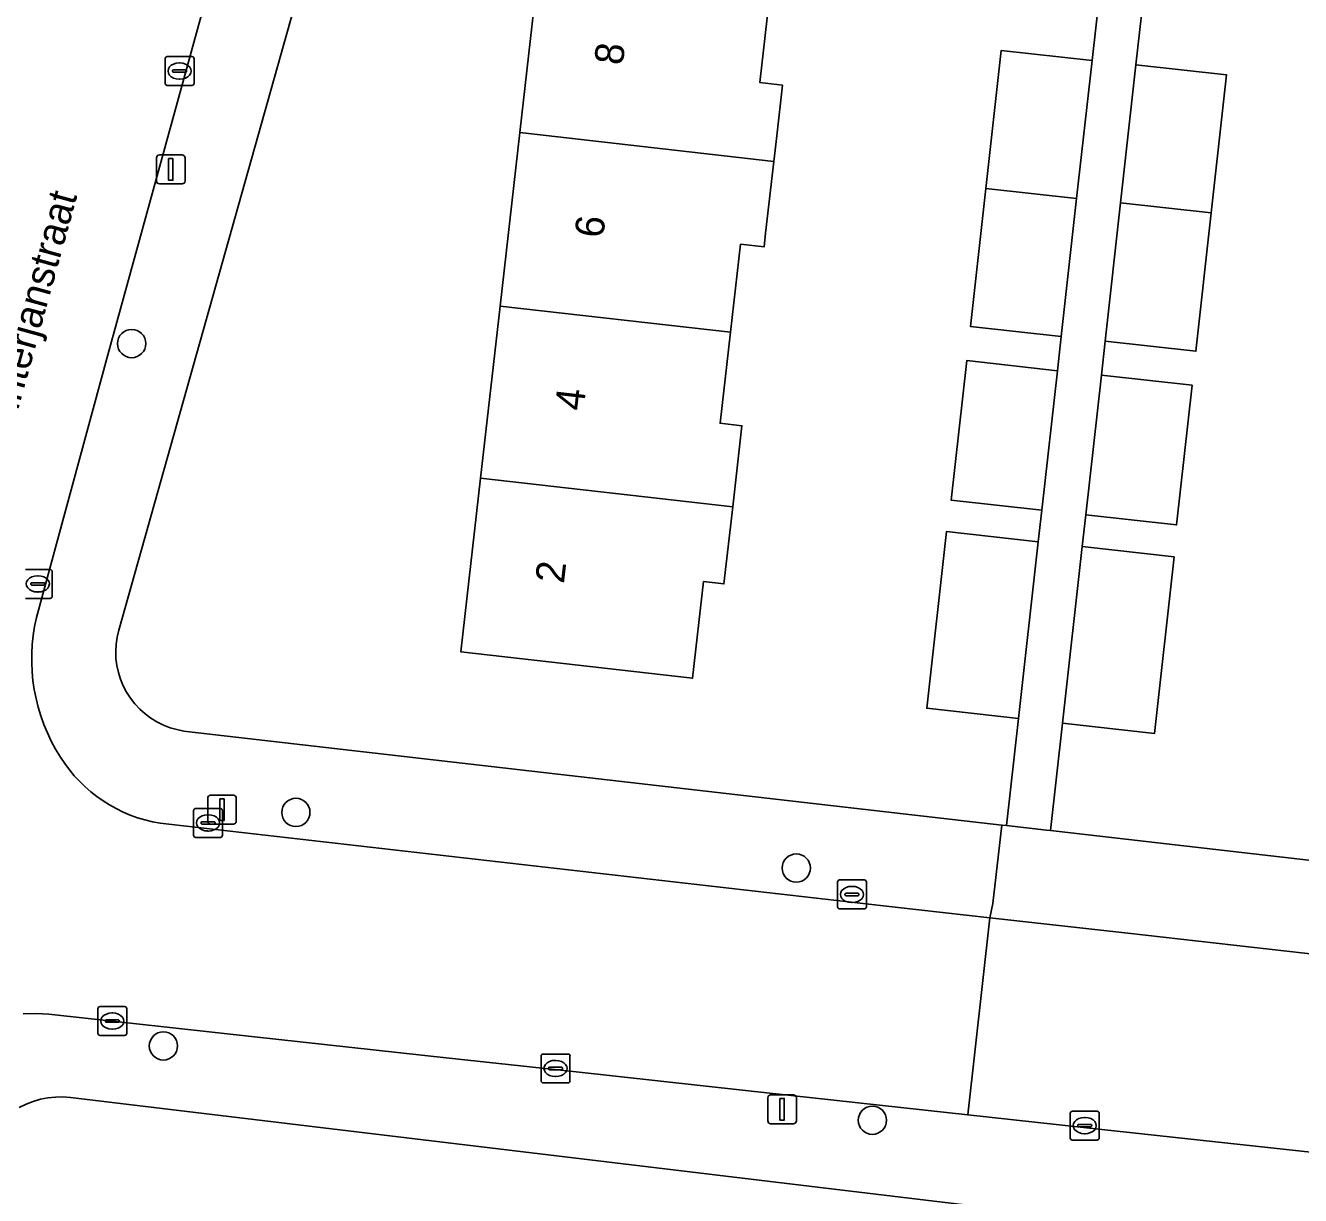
# Model space of a CAD drawing. Extents: x 162026 to 163502, y 387295 to 388169.
# Drawn here: x 162355.04 to 162399.19, y 387674.72 to 387715.23 of the extents above; entities that cross this region are included whole.
import ezdxf

# ---------------------------------------------------------------- set-up
doc = ezdxf.new("R2010")
doc.units = 0
for name, color, linetype in [('IMGEO_Boom', 7, 'Continuous'), ('IMGEO_Erf', 7, 'Continuous'), ('IMGEO_Kolk', 7, 'Continuous'), ('IMGEO_Lichtmast', 7, 'Continuous'), ('IMGEO_Openbare_ruimte_label', 7, 'Continuous'), ('IMGEO_Pand', 7, 'Continuous'), ('IMGEO_Pand_nummerreeks', 7, 'Continuous'), ('IMGEO_Rijbaan_lokaal_open', 7, 'Continuous'), ('IMGEO_Voetpad_open', 7, 'Continuous')]:
    doc.layers.add(name, color=color, linetype=linetype)

msp = doc.modelspace()

# ---------------------------------------------------------------- linework, layer by layer
at = {"layer": 'IMGEO_Boom'}
for centre in [(162358.717, 387704.216), (162364.402, 387687.982), (162381.73, 387686.057), (162359.815, 387679.899), (162384.363, 387677.325)]:
    msp.add_circle(centre, 0.489, dxfattribs=at)
at = {"layer": 'IMGEO_Erf'}
for points in [[(162369.363, 387733.695), (162358.268, 387694.296), (162358.211, 387694.055), (162358.176, 387693.81), (162358.163, 387693.562), (162358.172, 387693.315), (162358.204, 387693.069), (162358.257, 387692.827), (162358.331, 387692.591), (162358.427, 387692.362), (162358.542, 387692.143), (162358.676, 387691.935), (162358.829, 387691.74), (162358.998, 387691.559), (162359.183, 387691.394), (162359.382, 387691.247), (162359.593, 387691.117), (162359.815, 387691.007), (162360.046, 387690.917), (162360.284, 387690.849), (162360.527, 387690.801), (162360.613, 387690.79), (162388.85, 387687.545), (162389.013, 387687.526), (162389.427, 387691.233), (162386.247, 387691.587), (162386.929, 387697.705), (162390.109, 387697.35), (162390.232, 387698.447), (162387.091, 387698.797), (162387.63, 387703.627), (162390.771, 387703.277), (162390.902, 387704.455), (162387.762, 387704.805), (162388.295, 387709.586), (162388.828, 387714.366), (162391.969, 387714.016), (162392.234, 387716.39)], [(162405.775, 387731.887), (162398.802, 387732.687), (162398.12, 387726.557), (162394.939, 387726.911), (162394.814, 387725.788), (162397.955, 387725.438), (162397.423, 387720.658), (162396.89, 387715.867), (162393.749, 387716.217), (162393.488, 387713.868), (162396.629, 387713.519), (162396.097, 387708.738), (162395.564, 387703.95), (162392.423, 387704.299), (162392.292, 387703.124), (162395.433, 387702.775), (162394.895, 387697.939), (162391.754, 387698.288), (162391.631, 387697.184), (162394.812, 387696.83), (162394.131, 387690.714), (162390.951, 387691.068), (162390.537, 387687.351), (162410.507, 387685.056)], [(162380.837, 387716.521), (162380.466, 387713.255), (162381.25, 387713.166), (162381.05, 387711.409), (162380.949, 387710.524), (162380.667, 387708.041), (162380.613, 387707.564), (162379.797, 387707.656), (162379.45, 387704.609), (162379.092, 387701.456), (162379.849, 387701.37), (162379.529, 387698.56), (162379.226, 387695.893), (162378.519, 387695.973), (162378.139, 387692.627), (162370.115, 387693.539), (162370.798, 387699.552), (162371.475, 387705.514), (162372.158, 387711.522), (162372.829, 387717.43)], [(162386.507, 387674.529), (162356.601, 387678.112), (162356.339, 387678.132), (162356.076, 387678.128), (162355.815, 387678.1), (162355.557, 387678.05), (162355.305, 387677.976), (162355.06, 387677.88), (162354.825, 387677.763)]]:
    msp.add_lwpolyline(points, dxfattribs=at)
at = {"layer": 'IMGEO_Kolk'}
for p, q in [((162359.875, 387713.224), (162359.875, 387714.076)), ((162359.95, 387714.15), (162360.802, 387714.15)), ((162360.876, 387714.076), (162360.876, 387713.224)), ((162360.134, 387713.644), (162360.134, 387713.656)), ((162360.177, 387713.693), (162360.575, 387713.693)), ((162360.363, 387713.93), (162360.388, 387713.93)), ((162360.618, 387713.656), (162360.618, 387713.644)), ((162360.572, 387713.607), (162360.174, 387713.607)), ((162360.386, 387713.37), (162360.361, 387713.37)), ((162360.802, 387713.15), (162359.95, 387713.15)), ((162355.041, 387696.394), (162355.893, 387696.394)), ((162355.454, 387696.174), (162355.479, 387696.174)), ((162355.967, 387696.32), (162355.967, 387695.468)), ((162355.225, 387695.888), (162355.225, 387695.9)), ((162355.663, 387695.851), (162355.265, 387695.851)), ((162355.268, 387695.937), (162355.666, 387695.937)), ((162355.477, 387695.614), (162355.452, 387695.614)), ((162355.709, 387695.9), (162355.709, 387695.888)), ((162355.893, 387695.394), (162355.041, 387695.394)), ((162360.861, 387687.193), (162360.861, 387688.045)), ((162360.936, 387688.119), (162361.788, 387688.119)), ((162361.862, 387688.045), (162361.862, 387687.193)), ((162361.12, 387687.613), (162361.12, 387687.625)), ((162361.163, 387687.662), (162361.561, 387687.662)), ((162361.349, 387687.899), (162361.374, 387687.899)), ((162361.604, 387687.625), (162361.604, 387687.613)), ((162361.558, 387687.576), (162361.16, 387687.576)), ((162361.372, 387687.339), (162361.347, 387687.339)), ((162361.788, 387687.119), (162360.936, 387687.119)), ((162383.156, 387684.717), (162383.156, 387685.569)), ((162383.231, 387685.643), (162384.083, 387685.643)), ((162383.644, 387685.423), (162383.669, 387685.423)), ((162384.157, 387685.569), (162384.157, 387684.717)), ((162383.415, 387685.137), (162383.415, 387685.149)), ((162383.853, 387685.1), (162383.455, 387685.1)), ((162383.458, 387685.186), (162383.856, 387685.186)), ((162383.899, 387685.149), (162383.899, 387685.137)), ((162384.083, 387684.643), (162383.231, 387684.643)), ((162383.667, 387684.863), (162383.642, 387684.863)), ((162357.547, 387680.334), (162357.547, 387681.186)), ((162357.622, 387681.26), (162358.474, 387681.26)), ((162358.035, 387681.04), (162358.06, 387681.04)), ((162358.548, 387681.186), (162358.548, 387680.334)), ((162357.806, 387680.754), (162357.806, 387680.766)), ((162358.244, 387680.717), (162357.846, 387680.717)), ((162357.849, 387680.803), (162358.247, 387680.803)), ((162358.29, 387680.766), (162358.29, 387680.754)), ((162358.474, 387680.26), (162357.622, 387680.26)), ((162358.058, 387680.48), (162358.033, 387680.48)), ((162372.893, 387678.692), (162372.893, 387679.544)), ((162372.968, 387679.618), (162373.82, 387679.618)), ((162373.381, 387679.398), (162373.406, 387679.398)), ((162373.894, 387679.544), (162373.894, 387678.692)), ((162373.152, 387679.112), (162373.152, 387679.124)), ((162373.59, 387679.075), (162373.192, 387679.075)), ((162373.195, 387679.161), (162373.593, 387679.161)), ((162373.404, 387678.838), (162373.379, 387678.838)), ((162373.636, 387679.124), (162373.636, 387679.112)), ((162373.82, 387678.618), (162372.968, 387678.618)), ((162391.216, 387676.713), (162391.216, 387677.565)), ((162391.291, 387677.639), (162392.143, 387677.639)), ((162392.217, 387677.565), (162392.217, 387676.713)), ((162391.475, 387677.133), (162391.475, 387677.145)), ((162391.913, 387677.096), (162391.515, 387677.096)), ((162391.518, 387677.182), (162391.916, 387677.182)), ((162391.704, 387677.419), (162391.729, 387677.419)), ((162391.959, 387677.145), (162391.959, 387677.133)), ((162392.143, 387676.639), (162391.291, 387676.639)), ((162391.727, 387676.859), (162391.702, 387676.859))]:
    msp.add_line(p, q, dxfattribs=at)
for points in [[(162359.875, 387713.224), (162359.875, 387714.076)], [(162359.95, 387714.15), (162360.802, 387714.15)], [(162360.876, 387714.076), (162360.876, 387713.224)], [(162360.802, 387713.15), (162359.95, 387713.15)], [(162355.041, 387696.394), (162355.893, 387696.394)], [(162355.967, 387696.32), (162355.967, 387695.468)], [(162355.893, 387695.394), (162355.041, 387695.394)], [(162360.861, 387687.193), (162360.861, 387688.045)], [(162360.936, 387688.119), (162361.788, 387688.119)], [(162361.862, 387688.045), (162361.862, 387687.193)], [(162361.788, 387687.119), (162360.936, 387687.119)], [(162383.156, 387684.717), (162383.156, 387685.569)], [(162383.231, 387685.643), (162384.083, 387685.643)], [(162384.157, 387685.569), (162384.157, 387684.717)], [(162384.083, 387684.643), (162383.231, 387684.643)], [(162357.547, 387680.334), (162357.547, 387681.186)], [(162357.622, 387681.26), (162358.474, 387681.26)], [(162358.548, 387681.186), (162358.548, 387680.334)], [(162358.474, 387680.26), (162357.622, 387680.26)], [(162372.893, 387678.692), (162372.893, 387679.544)], [(162372.968, 387679.618), (162373.82, 387679.618)], [(162373.894, 387679.544), (162373.894, 387678.692)], [(162373.82, 387678.618), (162372.968, 387678.618)], [(162391.216, 387676.713), (162391.216, 387677.565)], [(162391.291, 387677.639), (162392.143, 387677.639)], [(162392.217, 387677.565), (162392.217, 387676.713)], [(162392.143, 387676.639), (162391.291, 387676.639)]]:
    msp.add_lwpolyline(points, dxfattribs=at)
for centre, radius, start, end in [((162359.952, 387714.074), 0.0765, 91.552, 178.448), ((162359.952, 387714.074), 0.0765, 91.552, 178.448), ((162360.8, 387714.074), 0.0765, 1.552, 88.448), ((162360.8, 387714.074), 0.0765, 1.552, 88.448), ((162360.174, 387713.653), 0.0403, 85.8775, 175.7526), ((162360.171, 387713.643), 0.0366, 178.938, 274.7102), ((162360.575, 387713.65), 0.043, 264.8664, 352.4533), ((162360.579, 387713.655), 0.0386, 1.7309, 96.639), ((162359.952, 387713.226), 0.0765, 181.552, 268.448), ((162359.952, 387713.226), 0.0765, 181.552, 268.448), ((162360.8, 387713.226), 0.0765, 271.552, 358.448), ((162360.8, 387713.226), 0.0765, 271.552, 358.448), ((162355.891, 387696.318), 0.0765, 1.552, 88.448), ((162355.891, 387696.318), 0.0765, 1.552, 88.448), ((162355.265, 387695.897), 0.0403, 85.8775, 175.7526), ((162355.262, 387695.887), 0.0366, 178.938, 274.7102), ((162355.666, 387695.894), 0.043, 264.8664, 352.4533), ((162355.67, 387695.899), 0.0386, 1.7309, 96.639), ((162355.891, 387695.47), 0.0765, 271.552, 358.448), ((162355.891, 387695.47), 0.0765, 271.552, 358.448), ((162360.938, 387688.043), 0.0765, 91.552, 178.448), ((162360.938, 387688.043), 0.0765, 91.552, 178.448), ((162361.786, 387688.043), 0.0765, 1.552, 88.448), ((162361.786, 387688.043), 0.0765, 1.552, 88.448), ((162361.16, 387687.622), 0.0403, 85.8775, 175.7526), ((162361.157, 387687.612), 0.0366, 178.938, 274.7102), ((162361.561, 387687.619), 0.043, 264.8664, 352.4533), ((162361.565, 387687.624), 0.0386, 1.7309, 96.639), ((162360.938, 387687.195), 0.0765, 181.552, 268.448), ((162360.938, 387687.195), 0.0765, 181.552, 268.448), ((162361.786, 387687.195), 0.0765, 271.552, 358.448), ((162361.786, 387687.195), 0.0765, 271.552, 358.448), ((162383.233, 387685.567), 0.0765, 91.552, 178.448), ((162383.233, 387685.567), 0.0765, 91.552, 178.448), ((162384.081, 387685.567), 0.0765, 1.552, 88.448), ((162384.081, 387685.567), 0.0765, 1.552, 88.448), ((162383.455, 387685.146), 0.0403, 85.8775, 175.7526), ((162383.452, 387685.136), 0.0366, 178.938, 274.7102), ((162383.856, 387685.143), 0.043, 264.8664, 352.4533), ((162383.86, 387685.148), 0.0386, 1.7309, 96.639), ((162383.233, 387684.719), 0.0765, 181.552, 268.448), ((162383.233, 387684.719), 0.0765, 181.552, 268.448), ((162384.081, 387684.719), 0.0765, 271.552, 358.448), ((162384.081, 387684.719), 0.0765, 271.552, 358.448), ((162357.624, 387681.184), 0.0765, 91.552, 178.448), ((162357.624, 387681.184), 0.0765, 91.552, 178.448), ((162358.472, 387681.184), 0.0765, 1.552, 88.448), ((162358.472, 387681.184), 0.0765, 1.552, 88.448), ((162357.846, 387680.763), 0.0403, 85.8775, 175.7526), ((162357.843, 387680.753), 0.0366, 178.938, 274.7102), ((162358.247, 387680.76), 0.043, 264.8664, 352.4533), ((162358.251, 387680.765), 0.0386, 1.7309, 96.639), ((162357.624, 387680.336), 0.0765, 181.552, 268.448), ((162357.624, 387680.336), 0.0765, 181.552, 268.448), ((162358.472, 387680.336), 0.0765, 271.552, 358.448), ((162358.472, 387680.336), 0.0765, 271.552, 358.448), ((162372.97, 387679.542), 0.0765, 91.552, 178.448), ((162372.97, 387679.542), 0.0765, 91.552, 178.448), ((162373.818, 387679.542), 0.0765, 1.552, 88.448), ((162373.818, 387679.542), 0.0765, 1.552, 88.448), ((162373.192, 387679.121), 0.0403, 85.8775, 175.7526), ((162373.189, 387679.111), 0.0366, 178.938, 274.7102), ((162373.593, 387679.118), 0.043, 264.8664, 352.4533), ((162373.597, 387679.123), 0.0386, 1.7309, 96.639), ((162372.97, 387678.694), 0.0765, 181.552, 268.448), ((162372.97, 387678.694), 0.0765, 181.552, 268.448), ((162373.818, 387678.694), 0.0765, 271.552, 358.448), ((162373.818, 387678.694), 0.0765, 271.552, 358.448), ((162391.293, 387677.563), 0.0765, 91.552, 178.448), ((162391.293, 387677.563), 0.0765, 91.552, 178.448), ((162392.141, 387677.563), 0.0765, 1.552, 88.448), ((162392.141, 387677.563), 0.0765, 1.552, 88.448), ((162391.515, 387677.142), 0.0403, 85.8775, 175.7526), ((162391.512, 387677.132), 0.0366, 178.938, 274.7102), ((162391.916, 387677.139), 0.043, 264.8664, 352.4533), ((162391.92, 387677.144), 0.0386, 1.7309, 96.639), ((162391.293, 387676.715), 0.0765, 181.552, 268.448), ((162391.293, 387676.715), 0.0765, 181.552, 268.448), ((162392.141, 387676.715), 0.0765, 271.552, 358.448), ((162392.141, 387676.715), 0.0765, 271.552, 358.448)]:
    msp.add_arc(centre, radius, start, end, dxfattribs=at)
for centre, major_axis, ratio, start_param, end_param in [((162360.362, 387713.65), (-0.387, 0.002), 0.722429, 4.712389, 7.853982), ((162360.387, 387713.65), (-0.39, 0.002), 0.717154, 1.570796, 4.712389), ((162355.453, 387695.894), (-0.387, 0.002), 0.722429, 4.712389, 7.853982), ((162355.478, 387695.894), (-0.39, 0.002), 0.717154, 1.570796, 4.712389), ((162361.348, 387687.619), (-0.387, 0.002), 0.722429, 4.712389, 7.853982), ((162361.373, 387687.619), (-0.39, 0.002), 0.717154, 1.570796, 4.712389), ((162383.643, 387685.143), (-0.387, 0.002), 0.722429, 4.712389, 7.853982), ((162383.668, 387685.143), (-0.39, 0.002), 0.717154, 1.570796, 4.712389), ((162358.034, 387680.76), (-0.387, 0.002), 0.722429, 4.712389, 7.853982), ((162358.059, 387680.76), (-0.39, 0.002), 0.717154, 1.570796, 4.712389), ((162373.38, 387679.118), (-0.387, 0.002), 0.722429, 4.712389, 7.853982), ((162373.405, 387679.118), (-0.39, 0.002), 0.717154, 1.570796, 4.712389), ((162391.703, 387677.139), (-0.387, 0.002), 0.722429, 4.712389, 7.853982), ((162391.728, 387677.139), (-0.39, 0.002), 0.717154, 1.570796, 4.712389)]:
    msp.add_ellipse(centre, major_axis=major_axis, ratio=ratio, start_param=start_param, end_param=end_param, dxfattribs=at)
at = {"layer": 'IMGEO_Lichtmast'}
for p, q in [((162359.575, 387709.844), (162359.575, 387710.644)), ((162359.575, 387710.644), (162359.575, 387709.844)), ((162359.675, 387710.744), (162360.465, 387710.744)), ((162360.465, 387710.744), (162359.675, 387710.744)), ((162360.565, 387710.644), (162360.565, 387709.844)), ((162360.565, 387709.844), (162360.565, 387710.644)), ((162360.465, 387709.744), (162359.675, 387709.744)), ((162359.675, 387709.744), (162360.465, 387709.744)), ((162361.349, 387687.677), (162361.349, 387688.477)), ((162361.349, 387688.477), (162361.349, 387687.677)), ((162361.449, 387688.577), (162362.239, 387688.577)), ((162362.239, 387688.577), (162361.449, 387688.577)), ((162362.339, 387688.477), (162362.339, 387687.677)), ((162362.339, 387687.677), (162362.339, 387688.477)), ((162362.239, 387687.577), (162361.449, 387687.577)), ((162361.449, 387687.577), (162362.239, 387687.577)), ((162380.742, 387677.304), (162380.742, 387678.104)), ((162380.742, 387678.104), (162380.742, 387677.304)), ((162380.842, 387678.204), (162381.632, 387678.204)), ((162381.632, 387678.204), (162380.842, 387678.204)), ((162381.732, 387678.104), (162381.732, 387677.304)), ((162381.732, 387677.304), (162381.732, 387678.104)), ((162381.632, 387677.204), (162380.842, 387677.204)), ((162380.842, 387677.204), (162381.632, 387677.204))]:
    msp.add_line(p, q, dxfattribs=at)
for points in [[(162359.995, 387710.619), (162360.145, 387710.619), (162360.145, 387709.869), (162359.995, 387709.869), (162359.995, 387710.619)], [(162361.769, 387688.452), (162361.919, 387688.452), (162361.919, 387687.702), (162361.769, 387687.702), (162361.769, 387688.452)], [(162381.162, 387678.079), (162381.312, 387678.079), (162381.312, 387677.329), (162381.162, 387677.329), (162381.162, 387678.079)]]:
    msp.add_lwpolyline(points, dxfattribs=at)
for centre, start, end in [((162359.675, 387710.644), 90, 180), ((162359.675, 387710.644), 90, 180), ((162360.465, 387710.644), 0, 90), ((162360.465, 387710.644), 360, 90), ((162359.675, 387709.844), 180, 270), ((162359.675, 387709.844), 180, 270), ((162360.465, 387709.844), 270, 0), ((162360.465, 387709.844), 270, 0), ((162361.449, 387688.477), 90, 180), ((162361.449, 387688.477), 90, 180), ((162362.239, 387688.477), 0, 90), ((162362.239, 387688.477), 360, 90), ((162361.449, 387687.677), 180, 270), ((162361.449, 387687.677), 180, 270), ((162362.239, 387687.677), 270, 0), ((162362.239, 387687.677), 270, 0), ((162380.842, 387678.104), 90, 180), ((162380.842, 387678.104), 90, 180), ((162381.632, 387678.104), 0, 90), ((162381.632, 387678.104), 360, 90), ((162380.842, 387677.304), 180, 270), ((162380.842, 387677.304), 180, 270), ((162381.632, 387677.304), 270, 0), ((162381.632, 387677.304), 270, 0)]:
    msp.add_arc(centre, 0.1, start, end, dxfattribs=at)
at = {"layer": 'IMGEO_Pand'}
for points in [[(162372.829, 387717.43), (162372.158, 387711.522), (162380.949, 387710.524), (162381.05, 387711.409), (162381.25, 387713.166), (162380.466, 387713.255), (162380.837, 387716.521)], [(162391.969, 387714.016), (162388.828, 387714.366), (162388.295, 387709.586), (162391.435, 387709.235)], [(162393.488, 387713.868), (162392.956, 387709.088), (162396.097, 387708.738), (162396.629, 387713.519)], [(162379.45, 387704.609), (162379.797, 387707.656), (162380.613, 387707.564), (162380.667, 387708.041), (162380.949, 387710.524), (162372.158, 387711.522), (162371.475, 387705.514)], [(162391.435, 387709.235), (162388.295, 387709.586), (162387.762, 387704.805), (162390.902, 387704.455)], [(162396.097, 387708.738), (162392.956, 387709.088), (162392.423, 387704.299), (162395.564, 387703.95)], [(162371.475, 387705.514), (162370.798, 387699.552), (162379.529, 387698.56), (162379.849, 387701.37), (162379.092, 387701.456), (162379.45, 387704.609)], [(162390.771, 387703.277), (162387.63, 387703.627), (162387.091, 387698.797), (162390.232, 387698.447)], [(162392.292, 387703.124), (162391.754, 387698.288), (162394.895, 387697.939), (162395.433, 387702.775)], [(162370.798, 387699.552), (162370.115, 387693.539), (162378.139, 387692.627), (162378.519, 387695.973), (162379.226, 387695.893), (162379.529, 387698.56)], [(162390.109, 387697.35), (162386.929, 387697.705), (162386.247, 387691.587), (162389.427, 387691.233)], [(162391.631, 387697.184), (162390.951, 387691.068), (162394.131, 387690.714), (162394.812, 387696.83)]]:
    msp.add_lwpolyline(points, close=True, dxfattribs=at)
at = {"layer": 'IMGEO_Rijbaan_lokaal_open'}
for points in [[(162355.418, 387694.735), (162357.89, 387703.825), (162366.165, 387733.888)], [(162388.435, 387684.336), (162385.158, 387684.707), (162359.698, 387687.605)], [(162354.965, 387681.013), (162355.405, 387681.025), (162355.844, 387680.998), (162362.969, 387680.217), (162369.61, 387679.49), (162373.999, 387679.009), (162379.974, 387678.355), (162387.668, 387677.512), (162388.435, 387684.336)], [(162410.331, 387681.861), (162393.205, 387683.797), (162388.435, 387684.336), (162387.668, 387677.512), (162392.308, 387677.004), (162411.245, 387674.951)]]:
    msp.add_lwpolyline(points, dxfattribs=at)
for centre, radius, start, end in [((162361.586, 387693.303), 6.332, 166.9314, 212.5231), ((162360.534, 387692.605), 5.069, 212.2628, 260.5105)]:
    msp.add_arc(centre, radius, start, end, dxfattribs=at)
at = {"layer": 'IMGEO_Voetpad_open'}
for points in [[(162354.825, 387677.763), (162355.06, 387677.88), (162355.305, 387677.976), (162355.557, 387678.05), (162355.815, 387678.1), (162356.076, 387678.128), (162356.339, 387678.132), (162356.601, 387678.112), (162386.507, 387674.529), (162391.724, 387673.904), (162393.448, 387673.699), (162419.619, 387670.747), (162425.088, 387670.179), (162433.168, 387742.074), (162432.585, 387742.149), (162431.245, 387742.321), (162427.027, 387742.863), (162362.56, 387750)], [(162366.165, 387733.888), (162357.89, 387703.825), (162355.418, 387694.735)], [(162359.698, 387687.605), (162385.158, 387684.707), (162388.435, 387684.336), (162388.53, 387684.829), (162388.85, 387687.545), (162360.613, 387690.79), (162360.527, 387690.801), (162360.284, 387690.849), (162360.046, 387690.917), (162359.815, 387691.007), (162359.593, 387691.117), (162359.382, 387691.247), (162359.183, 387691.394), (162358.998, 387691.559), (162358.829, 387691.74), (162358.676, 387691.935), (162358.542, 387692.143), (162358.427, 387692.362), (162358.331, 387692.591), (162358.257, 387692.827), (162358.204, 387693.069), (162358.172, 387693.315), (162358.163, 387693.562), (162358.176, 387693.81), (162358.211, 387694.055), (162358.268, 387694.296), (162369.363, 387733.695)], [(162392.234, 387716.39), (162391.969, 387714.016), (162391.435, 387709.235), (162390.902, 387704.455), (162390.771, 387703.277), (162390.232, 387698.447), (162390.109, 387697.35), (162389.427, 387691.233), (162389.013, 387687.526), (162390.397, 387687.367), (162390.537, 387687.351), (162390.951, 387691.068), (162391.631, 387697.184), (162391.754, 387698.288), (162392.292, 387703.124), (162392.423, 387704.299), (162392.956, 387709.088), (162393.488, 387713.868), (162393.749, 387716.217)], [(162410.507, 387685.056), (162390.537, 387687.351), (162390.397, 387687.367), (162389.013, 387687.526), (162388.85, 387687.545), (162388.53, 387684.829), (162388.435, 387684.336), (162393.205, 387683.797), (162410.331, 387681.861)], [(162411.245, 387674.951), (162392.308, 387677.004), (162387.668, 387677.512), (162379.974, 387678.355), (162373.999, 387679.009), (162369.61, 387679.49), (162362.969, 387680.217), (162355.844, 387680.998), (162355.405, 387681.025), (162354.965, 387681.013)]]:
    msp.add_lwpolyline(points, dxfattribs=at)
for centre, radius, start, end in [((162361.586, 387693.303), 6.332, 166.9314, 212.5231), ((162360.534, 387692.605), 5.069, 212.2628, 260.5105)]:
    msp.add_arc(centre, radius, start, end, dxfattribs=at)

# ---------------------------------------------------------------- texts
at = {"layer": 'IMGEO_Openbare_ruimte_label'}
msp.add_text('Winterjanstraat', height=1, rotation=74.574, dxfattribs=at).set_placement((162354.444, 387700.667))
at = {"layer": 'IMGEO_Pand_nummerreeks'}
for s, p in [('8', (162375.721, 387713.83)), ('6', (162375.042, 387707.846)), ('4', (162374.362, 387701.865)), ('2', (162373.682, 387695.883))]:
    msp.add_text(s, height=1, rotation=83.5198, dxfattribs=at).set_placement(p)

doc.saveas('drawing.dxf')
